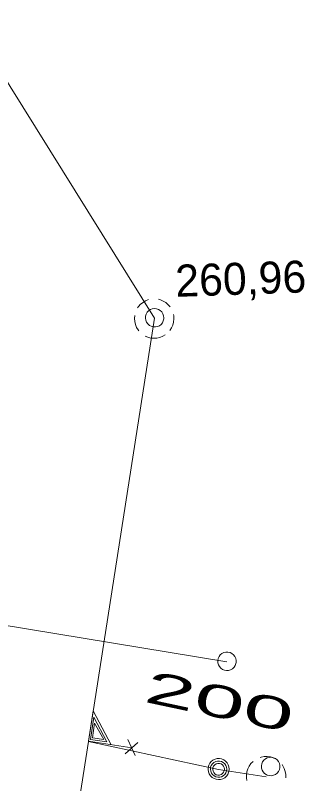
# Model space of a CAD drawing. Extents: x -732096 to -731933, y -1048703 to -1047964.
# Drawn here: x -732002.72 to -731995.49, y -1048134.02 to -1048114.82 of the extents above; entities that cross this region are included whole.
import ezdxf

# ---------------------------------------------------------------- set-up
doc = ezdxf.new("R2010")
doc.units = 0
doc.header["$LTSCALE"] = 0.32
doc.layers.add('1', color=7, linetype='Continuous')
for name, color, linetype, lineweight in [('18', 7, 'Continuous', 13), ('20', 7, 'Continuous', 13), ('49', 7, 'Continuous', 13), ('8', 7, 'Continuous', 13)]:
    doc.layers.add(name, color=color, linetype=linetype, lineweight=lineweight)

msp = doc.modelspace()

# ---------------------------------------------------------------- linework, layer by layer
at = {"layer": '18'}
for p, q in [((-731999.658, -1048132.99), (-731999.976, -1048133.28)), ((-731999.722, -1048133.322), (-731999.906, -1048132.918))]:
    msp.add_line(p, q, dxfattribs=at)
for points in [[(-731999.392, -1048121.927), (-731999.463, -1048121.955), (-731999.529, -1048121.994), (-731999.59, -1048122.042), (-731999.641, -1048122.099), (-731999.664, -1048122.133)], [(-731998.85, -1048122.11), (-731998.901, -1048122.052), (-731998.958, -1048122.002), (-731999.024, -1048121.961), (-731999.095, -1048121.932), (-731999.144, -1048121.918)], [(-731999.737, -1048122.319), (-731999.742, -1048122.396), (-731999.737, -1048122.473), (-731999.72, -1048122.548), (-731999.691, -1048122.619), (-731999.651, -1048122.685), (-731999.636, -1048122.707)], [(-731998.855, -1048122.696), (-731998.815, -1048122.631), (-731998.784, -1048122.561), (-731998.764, -1048122.486), (-731998.757, -1048122.41), (-731998.762, -1048122.333), (-731998.767, -1048122.298)], [(-731999.478, -1048122.836), (-731999.409, -1048122.867), (-731999.333, -1048122.886), (-731999.257, -1048122.893), (-731999.181, -1048122.888), (-731999.105, -1048122.871), (-731999.034, -1048122.843), (-731998.973, -1048122.808)], [(-731999.81, -1048133.128), (-732000.892, -1048132.959), (-732000.773, -1048132.199), (-732000.321, -1048133.049)], [(-732000.431, -1048132.981), (-732000.841, -1048132.917), (-732000.754, -1048132.358), (-732000.429, -1048132.981)], [(-732000.506, -1048132.922), (-732000.794, -1048132.876), (-732000.737, -1048132.509), (-732000.506, -1048132.923)], [(-731996.204, -1048133.41), (-731996.274, -1048133.377), (-731996.347, -1048133.354), (-731996.423, -1048133.343), (-731996.5, -1048133.344), (-731996.576, -1048133.358), (-731996.602, -1048133.365)], [(-731996.779, -1048133.465), (-731996.833, -1048133.519), (-731996.878, -1048133.583), (-731996.912, -1048133.651), (-731996.935, -1048133.725), (-731996.946, -1048133.801), (-731996.945, -1048133.878), (-731996.934, -1048133.947)], [(-731995.962, -1048133.873), (-731995.963, -1048133.796), (-731995.975, -1048133.72), (-731995.998, -1048133.647), (-731996.033, -1048133.579), (-731996.056, -1048133.544)]]:
    msp.add_lwpolyline(points, dxfattribs=at)
for points in [[(-731999.007, -1048122.379), (-731999.014, -1048122.327), (-731999.031, -1048122.277), (-731999.059, -1048122.233), (-731999.098, -1048122.196), (-731999.142, -1048122.169), (-731999.193, -1048122.153), (-731999.245, -1048122.148), (-731999.296, -1048122.155), (-731999.345, -1048122.174), (-731999.389, -1048122.204), (-731999.424, -1048122.243), (-731999.451, -1048122.288), (-731999.465, -1048122.339), (-731999.468, -1048122.391), (-731999.46, -1048122.443), (-731999.44, -1048122.491), (-731999.409, -1048122.534), (-731999.37, -1048122.569), (-731999.323, -1048122.593), (-731999.272, -1048122.607), (-731999.22, -1048122.609), (-731999.169, -1048122.599), (-731999.12, -1048122.577), (-731999.078, -1048122.545), (-731999.046, -1048122.505), (-731999.022, -1048122.458), (-731999.009, -1048122.407)], [(-731996.423, -1048133.809), (-731996.372, -1048133.822), (-731996.319, -1048133.823), (-731996.268, -1048133.813), (-731996.22, -1048133.791), (-731996.178, -1048133.758), (-731996.145, -1048133.717), (-731996.122, -1048133.671), (-731996.11, -1048133.62), (-731996.11, -1048133.567), (-731996.122, -1048133.515), (-731996.146, -1048133.468), (-731996.179, -1048133.428), (-731996.221, -1048133.396), (-731996.268, -1048133.374), (-731996.32, -1048133.363), (-731996.372, -1048133.365), (-731996.423, -1048133.378), (-731996.47, -1048133.403), (-731996.509, -1048133.437), (-731996.54, -1048133.48), (-731996.561, -1048133.528), (-731996.57, -1048133.58), (-731996.567, -1048133.632), (-731996.552, -1048133.683), (-731996.527, -1048133.728), (-731996.491, -1048133.767), (-731996.448, -1048133.797)], [(-731997.376, -1048133.657), (-731997.382, -1048133.601), (-731997.399, -1048133.548), (-731997.428, -1048133.499), (-731997.466, -1048133.458), (-731997.512, -1048133.426), (-731997.564, -1048133.404), (-731997.619, -1048133.393), (-731997.675, -1048133.395), (-731997.73, -1048133.408), (-731997.781, -1048133.433), (-731997.825, -1048133.468), (-731997.861, -1048133.511), (-731997.886, -1048133.561), (-731997.901, -1048133.616), (-731997.904, -1048133.672), (-731997.895, -1048133.727), (-731997.874, -1048133.78), (-731997.843, -1048133.826), (-731997.803, -1048133.865), (-731997.755, -1048133.895), (-731997.702, -1048133.914), (-731997.646, -1048133.921), (-731997.59, -1048133.917), (-731997.536, -1048133.9), (-731997.487, -1048133.873), (-731997.445, -1048133.835), (-731997.412, -1048133.79), (-731997.389, -1048133.739), (-731997.377, -1048133.684)], [(-731997.435, -1048133.66), (-731997.441, -1048133.611), (-731997.459, -1048133.565), (-731997.487, -1048133.524), (-731997.524, -1048133.491), (-731997.568, -1048133.469), (-731997.616, -1048133.457), (-731997.665, -1048133.457), (-731997.713, -1048133.469), (-731997.757, -1048133.492), (-731997.794, -1048133.525), (-731997.822, -1048133.566), (-731997.839, -1048133.613), (-731997.845, -1048133.662), (-731997.838, -1048133.711), (-731997.82, -1048133.757), (-731997.792, -1048133.797), (-731997.755, -1048133.83), (-731997.711, -1048133.852), (-731997.662, -1048133.864), (-731997.613, -1048133.863), (-731997.565, -1048133.851), (-731997.522, -1048133.827), (-731997.485, -1048133.794), (-731997.457, -1048133.753), (-731997.441, -1048133.706)], [(-731997.494, -1048133.664), (-731997.5, -1048133.622), (-731997.517, -1048133.584), (-731997.545, -1048133.553), (-731997.58, -1048133.53), (-731997.62, -1048133.519), (-731997.662, -1048133.519), (-731997.702, -1048133.531), (-731997.737, -1048133.554), (-731997.764, -1048133.586), (-731997.781, -1048133.624), (-731997.786, -1048133.665), (-731997.78, -1048133.707), (-731997.762, -1048133.744), (-731997.734, -1048133.776), (-731997.698, -1048133.798), (-731997.658, -1048133.809), (-731997.616, -1048133.808), (-731997.576, -1048133.795), (-731997.542, -1048133.772), (-731997.515, -1048133.739), (-731997.499, -1048133.701)]]:
    msp.add_lwpolyline(points, close=True, dxfattribs=at)
at = {"layer": '20'}
for points in [[(-731999.239, -1048122.39), (-732003.535, -1048115.515), (-732011.701, -1048102.444), (-732015.041, -1048097.097), (-732020.556, -1048088.271), (-732022.199, -1048085.64)], [(-731999.239, -1048122.39), (-732003.535, -1048115.515), (-732011.701, -1048102.444), (-732015.041, -1048097.097), (-732020.556, -1048088.271), (-732022.199, -1048085.64)], [(-732006.16, -1048166.67), (-732003.873, -1048152.041), (-732002.097, -1048140.675), (-732000.892, -1048132.965), (-731999.239, -1048122.39)], [(-732006.16, -1048166.67), (-732003.873, -1048152.041), (-732002.097, -1048140.675), (-732000.892, -1048132.965), (-731999.239, -1048122.39)]]:
    msp.add_lwpolyline(points, dxfattribs=at)
at = {"layer": '49'}
msp.add_lwpolyline([(-731996.449, -1048133.85), (-731997.64, -1048133.67), (-732000.892, -1048132.965)], dxfattribs=at)
msp.add_lwpolyline([(-731996.449, -1048133.85), (-731997.64, -1048133.67), (-732000.892, -1048132.965)], dxfattribs=at)
at = {"layer": '8'}
msp.add_line((-732004.579, -1048129.8), (-731997.432, -1048130.977), dxfattribs=at)
msp.add_lwpolyline([(-731997.201, -1048130.995), (-731997.2, -1048130.943), (-731997.212, -1048130.891), (-731997.234, -1048130.844), (-731997.266, -1048130.802), (-731997.307, -1048130.769), (-731997.355, -1048130.747), (-731997.406, -1048130.735), (-731997.458, -1048130.735), (-731997.509, -1048130.748), (-731997.557, -1048130.772), (-731997.597, -1048130.806), (-731997.628, -1048130.847), (-731997.65, -1048130.896), (-731997.66, -1048130.947), (-731997.659, -1048130.999), (-731997.644, -1048131.05), (-731997.62, -1048131.096), (-731997.585, -1048131.136), (-731997.542, -1048131.166), (-731997.494, -1048131.187), (-731997.442, -1048131.195), (-731997.39, -1048131.192), (-731997.339, -1048131.177), (-731997.293, -1048131.151), (-731997.255, -1048131.115), (-731997.225, -1048131.072), (-731997.207, -1048131.023)], close=True, dxfattribs=at)

# ---------------------------------------------------------------- texts
at = {"layer": '1'}
msp.add_text('260,96', height=0.8, rotation=2, dxfattribs=at).set_placement((-731998.709, -1048121.858))
at = {"layer": '1', "width": 2.1}
msp.add_text('200 ', height=0.8, rotation=348, dxfattribs=at).set_placement((-731999.532, -1048131.971))

doc.saveas('drawing.dxf')
